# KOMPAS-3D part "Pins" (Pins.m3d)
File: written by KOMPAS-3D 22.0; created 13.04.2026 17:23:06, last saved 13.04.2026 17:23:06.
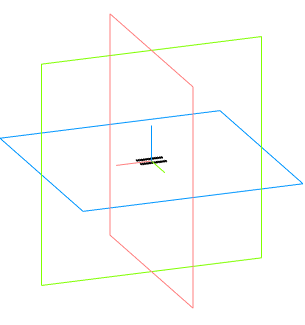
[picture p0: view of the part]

Document properties: Автор: Andrey; Полное имя файла: C:\Users\User1\Documents\Pins.m3d

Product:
- Part/product: Pins

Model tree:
1. Операция без истории:1
2. Операция без истории:2
3. Операция без истории:3
4. Операция без истории:4
5. Операция без истории:5
6. Операция без истории:6
7. Операция без истории:7
8. Операция без истории:8
9. Операция без истории:9
10. Операция без истории:10
11. Операция без истории:11
12. Операция без истории:12
13. Операция без истории:13
14. Операция без истории:14
15. Операция без истории:15
16. Операция без истории:16
17. Операция без истории:17
18. Операция без истории:18
19. Операция без истории:19
20. Операция без истории:20
21. Операция без истории:21
22. Операция без истории:22
23. Операция без истории:23
24. Операция без истории:24
25. Операция без истории:25
26. Операция без истории:26
27. Операция без истории:27
28. Операция без истории:28
29. Операция без истории:29
30. Операция без истории:30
